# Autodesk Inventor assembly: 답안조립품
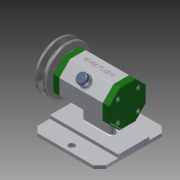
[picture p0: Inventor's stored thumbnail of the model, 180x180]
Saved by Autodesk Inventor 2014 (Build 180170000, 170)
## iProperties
Created: 2018-06
Part Number: 답안조립품
Document SubType Name: Assembly
Designer: kh
Author: kh
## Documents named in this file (16)
- C:\Users\kh\Desktop\480607V1010\답안조립품.iam
- C:\Users\kh\Desktop\480607V1010\본체.ipt
- C:\Users\kh\Desktop\480607V1010\축.ipt
- C:\Users\kh\Desktop\480607V1010\베어링 15x32x9.ipt
- C:\Users\kh\Desktop\480607V1010\뒤커버.ipt
- C:\Users\kh\Desktop\480607V1010\앞커버.ipt
- C:\Users\kh\Desktop\480607V1010\오일 실 15 25 7.ipt
- C:\Users\kh\Desktop\480607V1010\볼트 M4x12.ipt
- C:\Users\kh\Desktop\480607V1010\키 3x3x12.ipt
- 키 3x3x12.ipt
- C:\Users\kh\Desktop\480607V1010\V벨트풀리.ipt
- C:\Users\kh\Desktop\480607V1010\와셔 8x17.ipt
- C:\Users\kh\Desktop\480607V1010\스프링와셔 8.ipt
- C:\Users\kh\Desktop\480607V1010\너트 M8.ipt
- 너트 M8.ipt
- C:\Users\kh\Desktop\480607V1010\고무캡.ipt
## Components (2 placed, 2 different names)
1. V벨트풀리:1 — Insert:10, Mate:3, Insert:11
2. 고무캡:1 — Insert:14
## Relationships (4: Insert 3, Mate 1)
- Insert:10: V벨트풀리:1
- Mate:3: V벨트풀리:1
- Insert:11: V벨트풀리:1
- Insert:14: 고무캡:1
